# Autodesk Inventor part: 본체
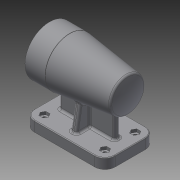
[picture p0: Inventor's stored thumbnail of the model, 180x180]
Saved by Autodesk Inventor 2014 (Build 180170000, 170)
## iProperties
Created: 2017-01
Part Number: 본체
Material: 일반
Document SubType Name: Modeling
Designer: user
Density: 1 g/cm^3
Appearance: 기본값
Author: user
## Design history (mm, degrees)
sketch "스케치2"
  geometry: L1 (-56, 35)-(56, 35); L2 (56, 35)-(56, -35); L3 (56, -35)-(-56, -35); L4 (-56, -35)-(-56, 35); L5 (-56, 35)-(56, -35); L6 (56, 35)-(-56, -35); 1 further point
  constraints: 12 end point, 2 midpoint, 2 parallel, 1 horizontal, 1 perpendicular
  dimensions: "d6" = 112 distance of L2.end L3.end; "d7" = 70 distance of L1.end L2.end
extrude "돌출1" new body sketch "스케치2" distance "d8" = 14; taper "d9" = 0 deg
fillet "모깎기2" dims "d10" = 14
fillet "모깎기3" dims "d11" = 14
sketch "스케치3"
  geometry: L1 (0, 0)-(0, 74); L2 (-56, 74)-(56, 74); L3 (56, 74)-(56, 108); L4 (56, 108)-(28, 108); L5 (28, 108)-(-52.27, 98.144); A1 r 80 centre (24, 74) between (-52.27, 98.144) and (-56, 74)
  constraints: 10 end point, 3 perpendicular, 2 point on circle, 1 centre point, 1 midpoint, 1 point on line, 1 vertical
  dimensions: "d12" = 74 distance of L1.end L1.start; "d13" = 68 diameter of L4 L2; "d14" = 28 distance from line of L4.end L3; "d15" = 7 deg angle of L5 L4; "d16" = 80 radius of A1; "d17" = 112 distance from line of L3 L2.start
revolve "회전2" sketch "스케치3" stored, may be unused: angle "d18" = 90 deg
sketch "스케치4"
  geometry: L1 (28, 40)-(28, 108) reference; L2 (56, 40)-(56, 108) reference; L3 (56, 74)-(-103.727, 74); L4 (56, 95)-(41, 95); L5 (41, 95)-(41, 95); L6 (38, 98)-(-10, 98); L7 (-13, 95)-(-13, 95); L8 (-13, 95)-(-24.7, 95); L9 (-25, 94.7)-(-25, 91.5); L10 (-25, 91.5)-(-42.7, 91.5); L11 (-43, 91.2)-(-43, 90); L12 (-43, 90)-(-46.7, 90); L13 (-47, 89.7)-(-47, 84.5); L14 (-47, 84.5)-(-47, 84.5); L15 (-50, 81.5)-(-50, 74); A1 r 0.3 centre (-46.7, 89.7) between (-46.7, 90) and (-47, 89.7); A2 r 0.3 centre (-42.7, 91.2) between (-42.7, 91.5) and (-43, 91.2); A3 r 0.3 centre (-24.7, 94.7) between (-24.7, 95) and (-25, 94.7); A4 r 3 centre (-47, 81.5) between (-47, 84.5) and (-50, 81.5); A5 r 3 centre (-10, 95) between (-10, 98) and (-13, 95); A6 r 3 centre (38, 95) between (41, 95) and (38, 98); 7 further points
  constraints: 26 end point, 14 point on line, 12 point on circle, 12 tangent, 10 perpendicular, 6 centre point, 4 equal radius, 3 parallel, 1 midpoint
  dimensions: "d20" = 42 diameter of L4 L3; "d21" = 48 diameter of L6 L3; "d22" = 42 diameter of L8 L3; "d23" = 35 diameter of L10 L3; "d24" = 32 diameter of L12 L3; "d25" = 15 distance of L4.start L4.end; "d26" = 54 distance of point (41, 98) point (-13, 98); "d27" = 12 distance of L7.end point (-25, 95); "d28" = 18 distance of L9.end point (-43, 91.5); "d29" = 4 distance of L11.end point (-47, 90); "d30" = 3 distance of L13.end point (-50, 84.5); "d31" = 21 diameter of L14 L3; "d32" = 0.3 radius of A1; "d33" = 3 radius of A4
revolve "회전3" sketch "스케치4" stored, may be unused: angle "d34" = 90 deg
sketch "스케치5"
  geometry: C1 r 34 at (0, 0) reference; A1 r 26 centre (0, 0) between (0, 26) and (26, 0); 3 further points
  constraints: 4 point on circle, 1 centre point, 1 coincident
  dimensions: "d35" = 52 diameter of A1
hole "구멍1" sketch "스케치5" at (0, 26), (26, 0), (0, -26), (-26, 0) diameter "d36" = 3.242; stored, may be unused: countersink angle "d40" = 90 deg, drill point angle "d42" = 118 deg; dims "d37" = 8, "d38" = 4, "d39" = 2, "d41" = 11
chamfer "모따기1" distance "d43" = 1; stored, may be unused: second distance "d44" = 2, angle "d45" = 45 deg
fillet "모깎기4" dims "d46" = 3
sketch "스케치6"
  geometry: L1 (56, -21)-(56, 21) reference; L2 (42, 35)-(-42, 35) reference; L3 (-56, 21)-(-56, -21) reference; L4 (-38, 4)-(38, 4); L5 (38, 4)-(38, -4); L6 (38, -4)-(-38, -4); L7 (-38, -4)-(-38, 4); L8 (-38, 4)-(38, -4); L9 (38, 4)-(-38, -4); 2 further points
  constraints: 12 end point, 3 midpoint, 2 parallel, 1 horizontal, 1 perpendicular
  dimensions: "d47" = 35 distance from line of point (0, 0) L2 (derived); "d48" = 8 distance between parallel lines of L6 L4; "d49" = 56 distance from line of point (0, 4) L1 (derived); "d50" = 18 distance between parallel lines of L5 L1; "d51" = 18 distance between parallel lines of L3 L7 (derived)
extrude "돌출2" join sketch "스케치6" stored distance "d52" = 14; taper "d53" = 0 deg
sketch "스케치7"
  geometry: L1 (21, 14)-(-21, 14) reference; L2 (-35, 0)-(-35, 14) reference; L3 (-35, 14)-(-21, 14) reference; L4 (35, 14)-(35, 0) reference; L5 (21, 14)-(35, 14) reference; L6 (35, 14)-(35, 0) reference; L7 (35, 0)-(21, 0) reference; L8 (21, 0)-(21, 14) reference; L9 (-15.923, 54.137)-(-23, 14); L10 (15.923, 54.137)-(23, 14); 1 further point
  constraints: 4 end point, 2 point on line
  dimensions: "d54" = 12 distance from line of L9.end L2; "d55" = 12 distance from line of L10.end L4; "d56" = 100 deg angle of L9 L3; "d57" = 100 deg angle of L10 L5; "d58" = 40.75605 distance of L9.start L9.end; "d59" = 40.756 distance of L10.start L10.end
  node "투영된 루프2"
feature "리브1" dims "d60" = 1, "d61" = 8, "d62" = 0, "d63" = 0, "d64" = 1, "d65" = 1
feature "리브2" dims "d66" = 1, "d67" = 8, "d68" = 0, "d69" = 0, "d70" = 1, "d71" = 1
fillet "모깎기5" dims "d72" = 3
fillet "모깎기6" dims "d73" = 3
fillet "모깎기7" dims "d74" = 3
sketch "스케치8"
  geometry: L1 (0, 0)-(84, 0) reference; L2 (-14, 0)-(-14, -14) reference; 2 further points
  constraints: 1 other
  dimensions: "d75" = 56 distance from line of point (42, -4) L2; "d76" = 4 distance from line of point (42, -4) L1
feature "엠보싱1" sketch "스케치8" dims "d6" = 112, "d7" = 70, "d12" = 74, "d13" = 68, "d14" = 28, "d15" = 7 deg, "d16" = 80, "d17" = 112, "d77" = 0.5, "d78" = 0
node "작업 평면1"
fillet "모깎기9" dims "d83" = 1
sketch "스케치9"
  geometry: L1 (-39.113, 26)-(-36.226, 21); L2 (-36.226, 21)-(-39.113, 16); L3 (-39.113, 16)-(-44.887, 16); L4 (-44.887, 16)-(-47.774, 21); L5 (-47.774, 21)-(-44.887, 26); L6 (-44.887, 26)-(-39.113, 26); L7 (36.226, 21)-(39.113, 26); L8 (44.887, 26)-(47.774, 21); L9 (47.774, 21)-(44.887, 16); L10 (44.887, 16)-(39.113, 16); L11 (39.113, 16)-(36.226, 21); L12 (39.113, -16)-(44.887, -16); L13 (36.226, -21)-(39.113, -16); L14 (44.887, -16)-(47.774, -21); L15 (47.774, -21)-(44.887, -26); L16 (44.887, -26)-(39.113, -26); L17 (39.113, -26)-(36.226, -21); L18 (-44.887, -16)-(-39.113, -16); L19 (-47.774, -21)-(-44.887, -16); L20 (-39.113, -16)-(-36.226, -21); L21 (-36.226, -21)-(-39.113, -26); L22 (-39.113, -26)-(-44.887, -26); L23 (-44.887, -26)-(-47.774, -21); L24 (39.113, 26)-(44.887, 26); A1 r 13 centre (-42, 21) between (-42, 34) and (-55, 21) reference; 5 further points
  constraints: 48 end point, 1 coincident, 1 parallel, 40 other
extrude "돌출3" cut sketch "스케치9" distance "d88" = 4; taper "d89" = 0 deg
sketch "스케치10"
  geometry: C1 r 2.5 at (-42, 21); C2 r 2.5 at (42, 21); C3 r 2.5 at (42, -21); C4 r 2.5 at (-42, -21); A1 r 14 centre (42, -21) between (42, -35) and (56, -21) reference; A2 r 14 centre (42, 21) between (56, 21) and (42, 35) reference; A3 r 14 centre (-42, 21) between (-42, 35) and (-56, 21) reference; A4 r 14 centre (-42, -21) between (-56, -21) and (-42, -35) reference; 1 further point
  constraints: 4 centre point, 4 coincident
  dimensions: "d90" = 5 diameter of C1; "d91" = 5 diameter of C2; "d92" = 5 diameter of C3; "d93" = 5 diameter of C4
extrude "돌출4" cut sketch "스케치10" stored distance "d94" = 4; taper "d95" = 0 deg
node "솔리드2"
node "투영된 루프1"
other parameters: "d81" = -7
